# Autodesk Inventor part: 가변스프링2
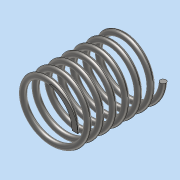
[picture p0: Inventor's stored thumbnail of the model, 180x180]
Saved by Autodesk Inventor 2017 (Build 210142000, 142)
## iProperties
Part Number: 가변스프링2
Material: 스테인레스 스틸
Document SubType Name: Modeling
Designer: MRC
Density: 8 g/cm^3
Appearance: 반연마
Mass: 10.9777 g
Surface Area: 27.6478 cm^2
Volume: 1.37221 cm^3
Author: MRC
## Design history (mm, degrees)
sketch "스케치1"
  geometry: L1 (0, 30.358)-(10, 30.358); L2 (10, 30.358)-(10, 0); L3 (10, 0)-(0, 0); L4 (0, 0)-(0, 30.358); C1 r 1 at (10, 0); 1 further point
  constraints: 8 end point, 2 coincident, 2 parallel, 1 centre point, 1 horizontal, 1 perpendicular
  dimensions: "d0" = 30.35829 distance of L1.end L2.end (derived); "d1" = 20 diameter of L2 L4; "d2" = 2 diameter of C1
feature "코일1" sketch "스케치1" pitch "d3" = 10; turns "d5" = 7; dims "d4" = 30.35829 (= d0), "d6" = 0, angle "d7" = 90 deg, angle "d8" = 90 deg, "d9" = 0, "d10" = 0
sketch "스케치2"
  geometry: L1 (-19.444, 50)-(19.444, 50); L2 (19.444, 50)-(19.444, 0); L3 (19.444, 0)-(-19.444, 0); L4 (-19.444, 0)-(-19.444, 50); 2 further points
  constraints: 8 end point, 2 parallel, 1 coincident, 1 horizontal, 1 midpoint, 1 perpendicular
  dimensions: "d11" = 50 distance of L1.end L2.end; "d12" = 38.88889 distance of L1.start L1.end
extrude "돌출1" sketch "스케치2" stored distance "d13" = 0; taper "d14" = 0 deg
node "솔리드1"
